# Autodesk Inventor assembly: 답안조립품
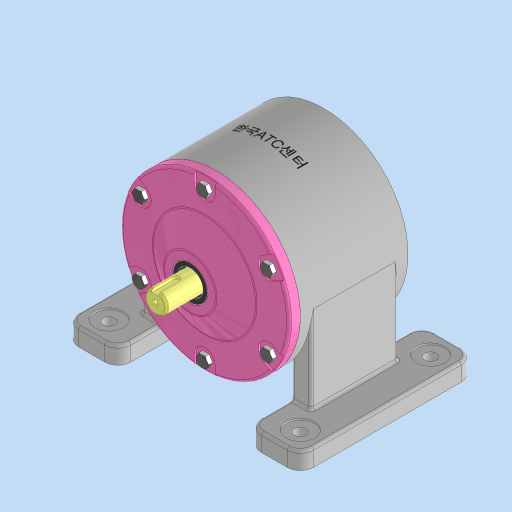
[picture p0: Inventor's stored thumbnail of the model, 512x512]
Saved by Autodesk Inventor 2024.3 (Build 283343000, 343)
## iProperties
Created: 2025-12
Part Number: 답안조립품
Document SubType Name: Assembly
Designer: PC2-02
Author: PC2-02
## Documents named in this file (17)
- C:\Users\PC2-02\Desktop\751203V1007\답안조립품.iam
- C:\Users\PC2-02\Desktop\751203V1007\본체.ipt
- C:\Users\PC2-02\Desktop\751203V1007\751203V1007\출력 축\출력 축.ipt
- C:\Users\PC2-02\Desktop\751203V1007\751203V1007\평행 키 6x6x16\평행 키 6x6x16.ipt
- C:\Users\PC2-02\Desktop\751203V1007\751203V1007\종동 기어\종동 기어.ipt
- C:\Users\PC2-02\Desktop\751203V1007\751203V1007\칼라 2\칼라 2.ipt
- C:\Users\PC2-02\Desktop\751203V1007\751203V1007\깊은 홈 볼 베어링 6004\깊은 홈 볼 베어링 6004.ipt
- C:\Users\PC2-02\Desktop\751203V1007\751203V1007\깊은 홈 볼 베어링 6005\깊은 홈 볼 베어링 6005.ipt
- C:\Users\PC2-02\Desktop\751203V1007\751203V1007\기어 축\기어 축.ipt
- C:\Users\PC2-02\Desktop\751203V1007\751203V1007\칼라 1\칼라 1.ipt
- C:\Users\PC2-02\Desktop\751203V1007\751203V1007\구동 기어\구동 기어.ipt
- C:\Users\PC2-02\Desktop\751203V1007\751203V1007\엔드 캡\엔드 캡.ipt
- C:\Users\PC2-02\Desktop\751203V1007\751203V1007\6각 구멍붙이 볼트 M4x10\6각 구멍붙이 볼트 M4x10.ipt
- C:\Users\PC2-02\Desktop\751203V1007\751203V1007\C형 멈춤링 구멍용 42\C형 멈춤링 구멍용 42.ipt
- C:\Users\PC2-02\Desktop\751203V1007\751203V1007\커버\커버.ipt
- C:\Users\PC2-02\Desktop\751203V1007\751203V1007\오일 실 25 40 8\오일 실 25 40 8.ipt
- C:\Users\PC2-02\Desktop\751203V1007\751203V1007\6각 머리 볼트 M8x20\6각 머리 볼트 M8x20.ipt
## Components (9 placed, 4 different names)
1. 구동 기어:1
2. 6각 구멍붙이 볼트 M4x10:1
3. C형 멈춤링 구멍용 42:1 — 각도:3
4. 6각 머리 볼트 M8x20:5
5. 6각 머리 볼트 M8x20:6
6. 6각 머리 볼트 M8x20:7
7. 6각 머리 볼트 M8x20:8
8. 6각 머리 볼트 M8x20:9
9. 6각 머리 볼트 M8x20:10
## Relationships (1: Angle 1)
- 각도:3 [Angle]: C형 멈춤링 구멍용 42:1
